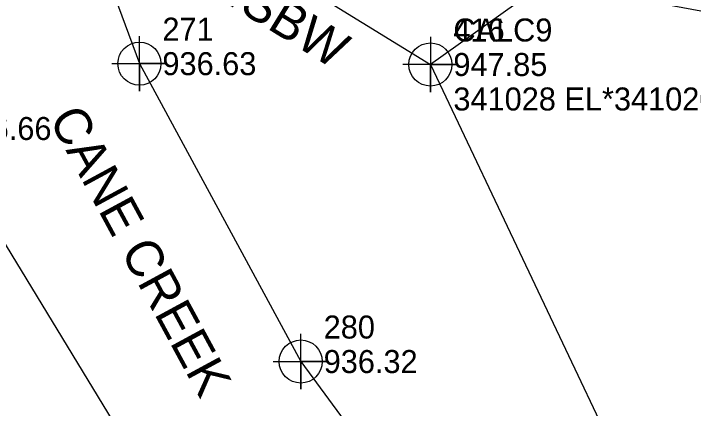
# Model space of a CAD drawing. Extents: x 1150279 to 1151282, y 655434 to 657999.
# Drawn here: x 1150767.1 to 1150841.1, y 657054.2 to 657097.1 of the extents above; entities that cross this region are included whole.
import ezdxf

# ---------------------------------------------------------------- set-up
doc = ezdxf.new("R2010")
doc.units = 0
for name, color, linetype in [('Exist Hydro Jurisdictional Stream or Body of Water', 7, 'Continuous'), ('Exist Hydro Jurisdictional Stream or Body of Water Text', 7, 'Continuous'), ('Exist Hydro Stream or Body of Water Cogo Elevation', 7, 'Continuous'), ('Exist Hydro Stream or Body of Water Cogo Number', 7, 'Continuous'), ('Exist Hydro Stream or Body of Water Cogo Point CELL', 7, 'Continuous'), ('Exist Other Culture Fence Line', 7, 'Continuous'), ('Exist Other Culture Fence Line Cogo Comment', 7, 'Continuous'), ('Exist Other Culture Fence Line Cogo Elevation', 7, 'Continuous'), ('Exist Other Culture Fence Line Cogo Number', 7, 'Continuous'), ('Exist Other Culture Fence Line Cogo Point CELL', 7, 'Continuous'), ('Exist Other Culture Fence Line Text', 7, 'Continuous')]:
    doc.layers.add(name, color=color, linetype=linetype)

msp = doc.modelspace()

# ---------------------------------------------------------------- linework, layer by layer
at = {"layer": 'Exist Hydro Jurisdictional Stream or Body of Water'}
for points in [[(1150769.348, 657125.308), (1150769.521, 657122.143), (1150780.786, 657091.685), (1150798.339, 657059.295), (1150820.355, 657029.39), (1150829.476, 657003.097)], [(1150745.794, 657124.778), (1150745.928, 657121.277), (1150758.485, 657084.636), (1150780.666, 657048.192), (1150800.517, 657025.21), (1150816.79, 656993.868)]]:
    msp.add_lwpolyline(points, dxfattribs=at)
at = {"layer": 'Exist Hydro Stream or Body of Water Cogo Point CELL'}
for points in [[(1150777.786, 657091.685), (1150783.786, 657091.685), (1150780.786, 657091.685), (1150780.786, 657088.685), (1150780.786, 657094.685)], [(1150795.339, 657059.295), (1150801.339, 657059.295), (1150798.339, 657059.295), (1150798.339, 657056.295), (1150798.339, 657062.295)]]:
    msp.add_lwpolyline(points, dxfattribs=at)
for centre in [(1150780.786, 657091.685), (1150798.339, 657059.295)]:
    msp.add_circle(centre, 2.344, dxfattribs=at)
at = {"layer": 'Exist Other Culture Fence Line'}
for points in [[(1150773.321, 657124.389), (1150794.109, 657102.9), (1150812.457, 657091.594)], [(1151064.379, 657042.204), (1151035.792, 657039.664), (1150986.531, 657050.151), (1150941.416, 657063.204), (1150898.391, 657078.653), (1150854.858, 657094.995), (1150825.025, 657100.534), (1150812.457, 657091.594), (1150835.172, 657043.741), (1150852.719, 657007.431)]]:
    msp.add_lwpolyline(points, dxfattribs=at)
at = {"layer": 'Exist Other Culture Fence Line Cogo Point CELL'}
msp.add_lwpolyline([(1150812.457, 657094.594), (1150812.457, 657088.594), (1150812.457, 657091.594), (1150815.457, 657091.594), (1150809.457, 657091.594)], dxfattribs=at)
msp.add_lwpolyline([(1150812.457, 657094.594), (1150812.457, 657088.594), (1150812.457, 657091.594), (1150815.457, 657091.594), (1150809.457, 657091.594)], dxfattribs=at)
msp.add_circle((1150812.457, 657091.594), 2.344, dxfattribs=at)
msp.add_circle((1150812.457, 657091.594), 2.344, dxfattribs=at)

# ---------------------------------------------------------------- texts
at = {"layer": 'Exist Hydro Jurisdictional Stream or Body of Water Text'}
msp.add_text('CANE CREEK', height=4, rotation=298.45461, dxfattribs=at).set_placement((1150770.87, 657085.692))
at = {"layer": 'Exist Hydro Stream or Body of Water Cogo Elevation'}
for s, p in [('936.63', (1150783.286, 657090.435)), ('936.66', (1150760.985, 657083.386)), ('936.32', (1150800.839, 657058.045))]:
    msp.add_text(s, height=2.5, dxfattribs=at).set_placement(p)
at = {"layer": 'Exist Hydro Stream or Body of Water Cogo Number'}
for s, p in [('271', (1150783.286, 657094.185)), ('280', (1150800.839, 657061.795))]:
    msp.add_text(s, height=2.5, dxfattribs=at).set_placement(p)
at = {"layer": 'Exist Other Culture Fence Line Cogo Comment'}
msp.add_text('341028 EL*341020', height=2.5, dxfattribs=at).set_placement((1150814.957, 657086.594))
at = {"layer": 'Exist Other Culture Fence Line Cogo Elevation'}
msp.add_text('947.85', height=2.5, dxfattribs=at).set_placement((1150814.957, 657090.344))
msp.add_text('947.85', height=2.5, dxfattribs=at).set_placement((1150814.957, 657090.344))
at = {"layer": 'Exist Other Culture Fence Line Cogo Number'}
for s in ['416', 'CALC9']:
    msp.add_text(s, height=2.5, dxfattribs=at).set_placement((1150814.957, 657094.094))
at = {"layer": 'Exist Other Culture Fence Line Text'}
msp.add_text('4SBW', height=4, rotation=328.35803, dxfattribs=at).set_placement((1150788.996, 657099.003))

doc.saveas('drawing.dxf')
